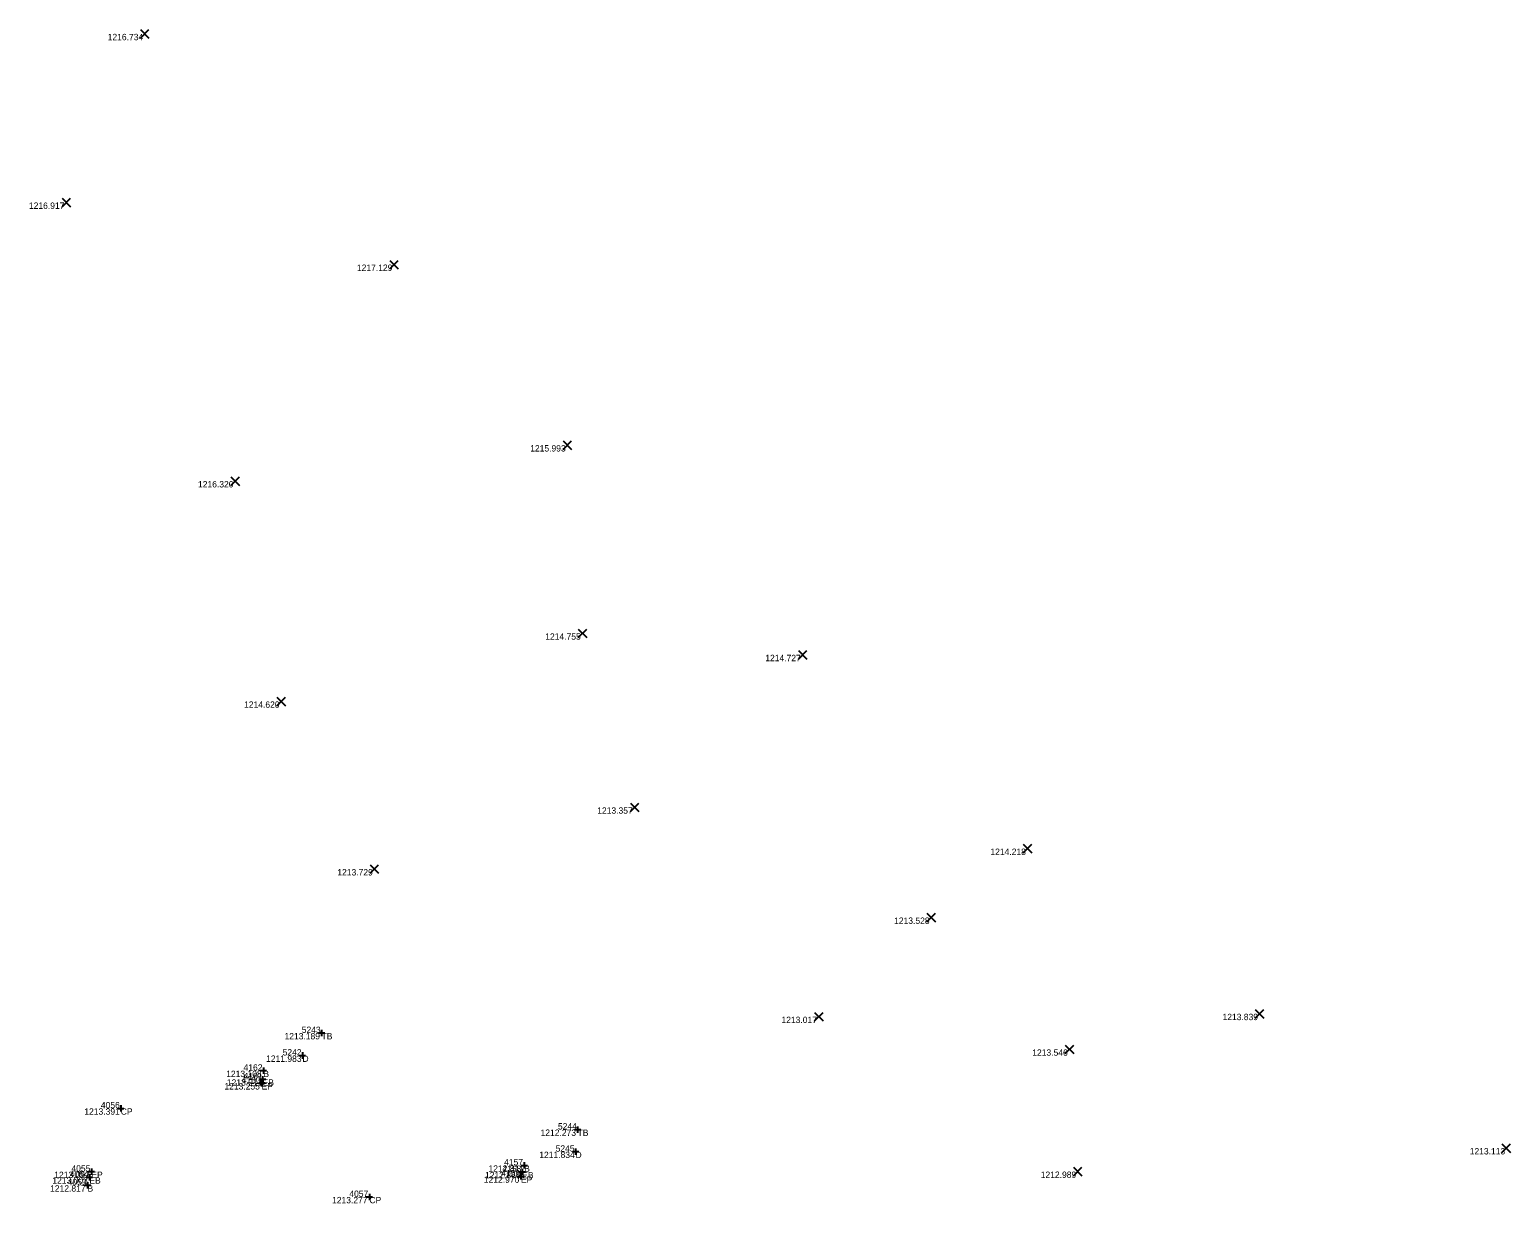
# Model space of a CAD drawing. Extents: x 2044997 to 2050342, y 455233 to 458054.
# Drawn here: x 2047991.1 to 2048223.9, y 456844.5 to 457029.1 of the extents above; entities that cross this region are included whole.
import ezdxf

# ---------------------------------------------------------------- set-up
doc = ezdxf.new("R2010")
doc.units = 0
for name, color, linetype in [('SV_X_Random_Point', 7, 'Continuous'), ('SV_X_Shot_Marker', 7, 'Continuous'), ('SV_X_Text_Comment', 7, 'Continuous'), ('SV_X_Text_Elevation', 7, 'Continuous'), ('SV_X_Text_Name', 7, 'Continuous')]:
    doc.layers.add(name, color=color, linetype=linetype)

msp = doc.modelspace()

# ---------------------------------------------------------------- linework, layer by layer
at = {"layer": 'SV_X_Random_Point'}
for p, q in [((2048008.54, 457027.76), (2048009.87, 457029.1)), ((2048008.54, 457029.1), (2048009.87, 457027.76)), ((2047996.24, 457001.24), (2047997.57, 457002.58)), ((2047996.24, 457002.58), (2047997.57, 457001.24)), ((2048047.73, 456991.48), (2048049.06, 456992.81)), ((2048047.73, 456992.81), (2048049.06, 456991.48)), ((2048074.98, 456963.08), (2048076.32, 456964.41)), ((2048074.98, 456964.41), (2048076.32, 456963.08)), ((2048022.77, 456957.43), (2048024.11, 456958.76)), ((2048022.77, 456958.76), (2048024.11, 456957.43)), ((2048077.37, 456933.49), (2048078.71, 456934.82)), ((2048077.37, 456934.82), (2048078.71, 456933.49)), ((2048111.99, 456930.11), (2048113.33, 456931.45)), ((2048111.99, 456931.45), (2048113.33, 456930.11)), ((2048030.01, 456922.78), (2048031.34, 456924.12)), ((2048030.01, 456924.12), (2048031.34, 456922.78)), ((2048085.57, 456906.12), (2048086.91, 456907.45)), ((2048085.57, 456907.45), (2048086.91, 456906.12)), ((2048147.34, 456899.64), (2048148.68, 456900.98)), ((2048147.34, 456900.98), (2048148.68, 456899.64)), ((2048044.65, 456896.42), (2048045.98, 456897.75)), ((2048044.65, 456897.75), (2048045.98, 456896.42)), ((2048132.2, 456888.8), (2048133.54, 456890.14)), ((2048132.2, 456890.14), (2048133.54, 456888.8)), ((2048114.54, 456873.21), (2048115.87, 456874.54)), ((2048114.54, 456874.54), (2048115.87, 456873.21)), ((2048183.81, 456873.66), (2048185.15, 456874.99)), ((2048183.81, 456874.99), (2048185.15, 456873.66)), ((2048153.93, 456868.06), (2048155.26, 456869.4)), ((2048153.93, 456869.4), (2048155.26, 456868.06)), ((2048222.58, 456852.54), (2048223.91, 456853.88)), ((2048222.58, 456853.88), (2048223.91, 456852.54)), ((2048155.23, 456848.85), (2048156.56, 456850.19)), ((2048155.23, 456850.19), (2048156.56, 456848.85))]:
    msp.add_line(p, q, dxfattribs=at)
at = {"layer": 'SV_X_Shot_Marker'}
for p, q in [((2048036.52, 456871.31), (2048037.52, 456871.31)), ((2048037.02, 456871.81), (2048037.02, 456870.81)), ((2048037.02, 456871.31), (2048037.02, 456871.31)), ((2048033.52, 456867.77), (2048034.52, 456867.77)), ((2048034.02, 456868.27), (2048034.02, 456867.27)), ((2048034.02, 456867.77), (2048034.02, 456867.77)), ((2048027.26, 456864.03), (2048028.26, 456864.03)), ((2048027.37, 456865.39), (2048028.37, 456865.39)), ((2048027.76, 456864.53), (2048027.76, 456863.53)), ((2048027.76, 456864.03), (2048027.76, 456864.03)), ((2048027.87, 456865.89), (2048027.87, 456864.89)), ((2048027.87, 456865.39), (2048027.87, 456865.39)), ((2048027.09, 456863.42), (2048028.09, 456863.42)), ((2048027.59, 456863.92), (2048027.59, 456862.92)), ((2048027.59, 456863.42), (2048027.59, 456863.42)), ((2048004.95, 456859.46), (2048005.95, 456859.46)), ((2048005.45, 456859.96), (2048005.45, 456858.96)), ((2048005.45, 456859.46), (2048005.45, 456859.46)), ((2048076.77, 456856.13), (2048077.77, 456856.13)), ((2048077.27, 456856.63), (2048077.27, 456855.63)), ((2048077.27, 456856.13), (2048077.27, 456856.13)), ((2048076.45, 456852.65), (2048077.45, 456852.65)), ((2048076.95, 456853.15), (2048076.95, 456852.15)), ((2048076.95, 456852.65), (2048076.95, 456852.65)), ((2048068.38, 456850.49), (2048069.38, 456850.49)), ((2048068.88, 456850.99), (2048068.88, 456849.99)), ((2048068.88, 456850.49), (2048068.88, 456850.49)), ((2048000.02, 456848.62), (2048001.02, 456848.62)), ((2048000.23, 456847.87), (2048000.23, 456846.87)), ((2048000.33, 456849.51), (2048001.33, 456849.51)), ((2048000.52, 456849.12), (2048000.52, 456848.12)), ((2048000.52, 456848.62), (2048000.52, 456848.62)), ((2048000.83, 456850.01), (2048000.83, 456849.01)), ((2048000.83, 456849.51), (2048000.83, 456849.51)), ((2048067.87, 456848.75), (2048068.87, 456848.75)), ((2048068.06, 456849.46), (2048069.06, 456849.46)), ((2048068.37, 456849.25), (2048068.37, 456848.25)), ((2048068.37, 456848.75), (2048068.37, 456848.75)), ((2048068.56, 456849.96), (2048068.56, 456848.96)), ((2048068.56, 456849.46), (2048068.56, 456849.46)), ((2047999.73, 456847.37), (2048000.73, 456847.37)), ((2048000.23, 456847.37), (2048000.23, 456847.37)), ((2048044.05, 456845.53), (2048045.05, 456845.53)), ((2048044.55, 456846.03), (2048044.55, 456845.03)), ((2048044.55, 456845.53), (2048044.55, 456845.53))]:
    msp.add_line(p, q, dxfattribs=at)

# ---------------------------------------------------------------- texts
at = {"layer": 'SV_X_Text_Comment'}
for s, p in [('TB', (2048037.02, 456870.31)), ('D', (2048034.02, 456866.77)), ('EB', (2048027.76, 456863.03)), ('B', (2048027.87, 456864.39)), ('EP', (2048027.59, 456862.42)), ('CP', (2048005.45, 456858.46)), ('TB', (2048077.27, 456855.13)), ('D', (2048076.95, 456851.65)), ('B', (2048068.88, 456849.49)), ('EB', (2048000.52, 456847.62)), ('EP', (2048000.83, 456848.51)), ('EP', (2048068.37, 456847.75)), ('EB', (2048068.56, 456848.46)), ('B', (2048000.23, 456846.37)), ('CP', (2048044.55, 456844.53))]:
    msp.add_text(s, height=1, dxfattribs=at).set_placement(p)
at = {"layer": 'SV_X_Text_Elevation'}
for s, p in [('1216.734', (2048003.4, 457027.43)), ('1216.917', (2047991.02, 457000.91)), ('1217.129', (2048042.58, 456991.15)), ('1215.993', (2048069.82, 456962.75)), ('1216.320', (2048017.6, 456957.1)), ('1214.755', (2048072.19, 456933.16)), ('1214.727', (2048106.78, 456929.78)), ('1214.620', (2048024.84, 456922.45)), ('1213.357', (2048080.36, 456905.79)), ('1214.218', (2048142.17, 456899.31)), ('1213.729', (2048039.5, 456896.08)), ('1213.528', (2048127.03, 456888.47)), ('1213.017', (2048109.32, 456872.87)), ('1213.839', (2048178.66, 456873.33)), ('1213.189', (2048031.2, 456870.31)), ('1213.546', (2048148.75, 456867.73)), ('1211.983', (2048028.3, 456866.77)), ('1213.108', (2048022.03, 456864.39)), ('1213.211', (2048022.14, 456863.03)), ('1213.255', (2048021.75, 456862.42)), ('1213.391', (2047999.73, 456858.46)), ('1212.273', (2048071.45, 456855.13)), ('1211.834', (2048071.25, 456851.65)), ('1213.113', (2048217.52, 456852.21)), ('1212.811', (2048063.26, 456849.49)), ('1213.003', (2047994.7, 456847.62)), ('1213.092', (2047995, 456848.51)), ('1212.970', (2048062.53, 456847.75)), ('1212.866', (2048062.72, 456848.46)), ('1212.989', (2048150.08, 456848.52)), ('1212.817', (2047994.35, 456846.37)), ('1213.277', (2048038.67, 456844.53))]:
    msp.add_text(s, height=1, dxfattribs=at).set_placement(p)
at = {"layer": 'SV_X_Text_Name'}
for s, p in [('5243', (2048033.91, 456871.31)), ('5242', (2048030.9, 456867.77)), ('4162', (2048024.76, 456865.39)), ('4160', (2048024.47, 456863.42)), ('4161', (2048024.76, 456864.03)), ('4056', (2048002.33, 456859.46)), ('5244', (2048074.18, 456856.13)), ('5245', (2048073.82, 456852.65)), ('4055', (2047997.7, 456849.51)), ('4158', (2048065.45, 456849.46)), ('4157', (2048065.72, 456850.49)), ('4053', (2047997.12, 456847.37)), ('4054', (2047997.43, 456848.62)), ('4159', (2048065.27, 456848.75)), ('4057', (2048041.39, 456845.53))]:
    msp.add_text(s, height=1, dxfattribs=at).set_placement(p)

doc.saveas('drawing.dxf')
